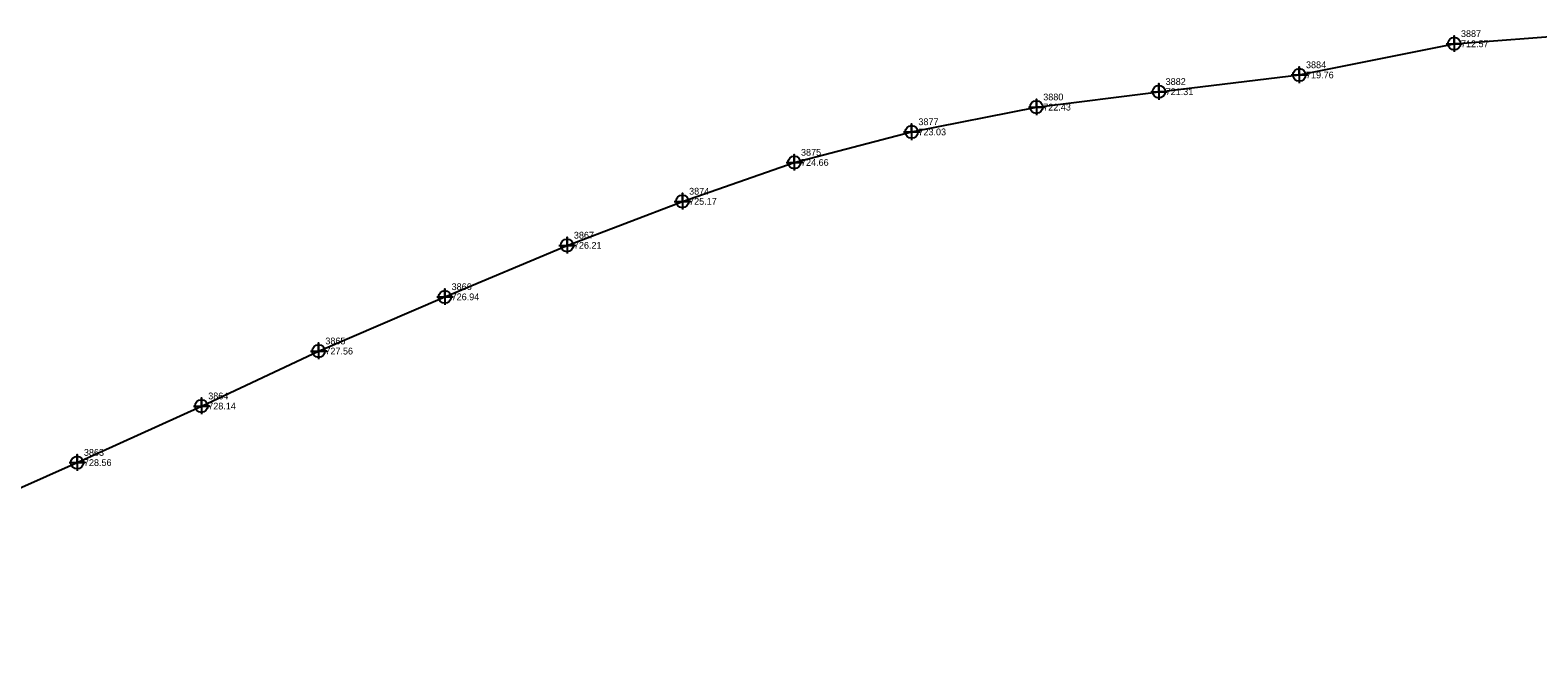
# Model space of a CAD drawing. Extents: x 1622486 to 1624761, y 758733 to 760816.
# Drawn here: x 1623638 to 1624195, y 759832 to 760058 of the extents above; entities that cross this region are included whole.
import ezdxf

# ---------------------------------------------------------------- set-up
doc = ezdxf.new("R2010")
doc.units = 0
for name, color, linetype in [('Exist Utilities Gas UG Line SUE', 7, 'Continuous'), ('Exist Utilities Gas UG Line SUE Cogo Elevation', 7, 'Continuous'), ('Exist Utilities Gas UG Line SUE Cogo Number', 7, 'Continuous'), ('Exist Utilities Gas UG Line SUE Cogo Point CELL', 7, 'Continuous')]:
    doc.layers.add(name, color=color, linetype=linetype)

msp = doc.modelspace()

# ---------------------------------------------------------------- linework, layer by layer
at = {"layer": 'Exist Utilities Gas UG Line SUE'}
msp.add_lwpolyline([(1623526, 759831.96), (1623567.48, 759856.55), (1623610.76, 759878.94), (1623655.07, 759898.59), (1623701.03, 759919.48), (1623744.33, 759939.8), (1623791, 759959.85), (1623836.2, 759978.89), (1623878.8, 759995.14), (1623920.16, 760009.52), (1623963.56, 760020.82), (1624009.71, 760029.98), (1624054.96, 760035.68), (1624106.85, 760041.87), (1624164.13, 760053.39), (1624209.29, 760056.8), (1624221.97, 760056.55), (1624280.33, 760056.28), (1624310.83, 760055.98), (1624347.04, 760055.47), (1624394.66, 760052.45), (1624442.78, 760047.24), (1624444.88, 760047.16)], dxfattribs=at)
at = {"layer": 'Exist Utilities Gas UG Line SUE Cogo Point CELL'}
for points in [[(1624161.13, 760053.39), (1624167.13, 760053.39), (1624164.13, 760053.39), (1624164.13, 760056.39), (1624164.13, 760050.39)], [(1624103.85, 760041.87), (1624109.85, 760041.87), (1624106.85, 760041.87), (1624106.85, 760044.87), (1624106.85, 760038.87)], [(1624051.96, 760035.68), (1624057.96, 760035.68), (1624054.96, 760035.68), (1624054.96, 760038.68), (1624054.96, 760032.68)], [(1624006.71, 760029.98), (1624012.71, 760029.98), (1624009.71, 760029.98), (1624009.71, 760032.98), (1624009.71, 760026.98)], [(1623960.56, 760020.82), (1623966.56, 760020.82), (1623963.56, 760020.82), (1623963.56, 760023.82), (1623963.56, 760017.82)], [(1623917.16, 760009.52), (1623923.16, 760009.52), (1623920.16, 760009.52), (1623920.16, 760012.52), (1623920.16, 760006.52)], [(1623875.8, 759995.14), (1623881.8, 759995.14), (1623878.8, 759995.14), (1623878.8, 759998.14), (1623878.8, 759992.14)], [(1623833.2, 759978.89), (1623839.2, 759978.89), (1623836.2, 759978.89), (1623836.2, 759981.89), (1623836.2, 759975.89)], [(1623788, 759959.85), (1623794, 759959.85), (1623791, 759959.85), (1623791, 759962.85), (1623791, 759956.85)], [(1623741.33, 759939.8), (1623747.33, 759939.8), (1623744.33, 759939.8), (1623744.33, 759942.8), (1623744.33, 759936.8)], [(1623698.03, 759919.48), (1623704.03, 759919.48), (1623701.03, 759919.48), (1623701.03, 759922.48), (1623701.03, 759916.48)], [(1623652.07, 759898.59), (1623658.07, 759898.59), (1623655.07, 759898.59), (1623655.07, 759901.59), (1623655.07, 759895.59)]]:
    msp.add_lwpolyline(points, dxfattribs=at)
for centre in [(1624164.13, 760053.39), (1624106.85, 760041.87), (1624054.96, 760035.68), (1624009.71, 760029.98), (1623963.56, 760020.82), (1623920.16, 760009.52), (1623878.8, 759995.14), (1623836.2, 759978.89), (1623791, 759959.85), (1623744.33, 759939.8), (1623701.03, 759919.48), (1623655.07, 759898.59)]:
    msp.add_circle(centre, 2.34, dxfattribs=at)

# ---------------------------------------------------------------- texts
at = {"layer": 'Exist Utilities Gas UG Line SUE Cogo Elevation'}
for s, p in [('712.57', (1624166.63, 760052.14)), ('719.76', (1624109.35, 760040.62)), ('721.31', (1624057.46, 760034.43)), ('722.43', (1624012.21, 760028.73)), ('723.03', (1623966.06, 760019.57)), ('724.66', (1623922.66, 760008.27)), ('725.17', (1623881.3, 759993.89)), ('726.21', (1623838.7, 759977.64)), ('726.94', (1623793.5, 759958.6)), ('727.56', (1623746.83, 759938.55)), ('728.14', (1623703.53, 759918.23)), ('728.56', (1623657.57, 759897.34))]:
    msp.add_text(s, height=2.5, dxfattribs=at).set_placement(p)
at = {"layer": 'Exist Utilities Gas UG Line SUE Cogo Number'}
for s, p in [('3887', (1624166.63, 760055.89)), ('3884', (1624109.35, 760044.37)), ('3882', (1624057.46, 760038.18)), ('3880', (1624012.21, 760032.48)), ('3877', (1623966.06, 760023.32)), ('3875', (1623922.66, 760012.02)), ('3874', (1623881.3, 759997.64)), ('3867', (1623838.7, 759981.39)), ('3866', (1623793.5, 759962.35)), ('3865', (1623746.83, 759942.3)), ('3864', (1623703.53, 759921.98)), ('3863', (1623657.57, 759901.09))]:
    msp.add_text(s, height=2.5, dxfattribs=at).set_placement(p)

doc.saveas('drawing.dxf')
